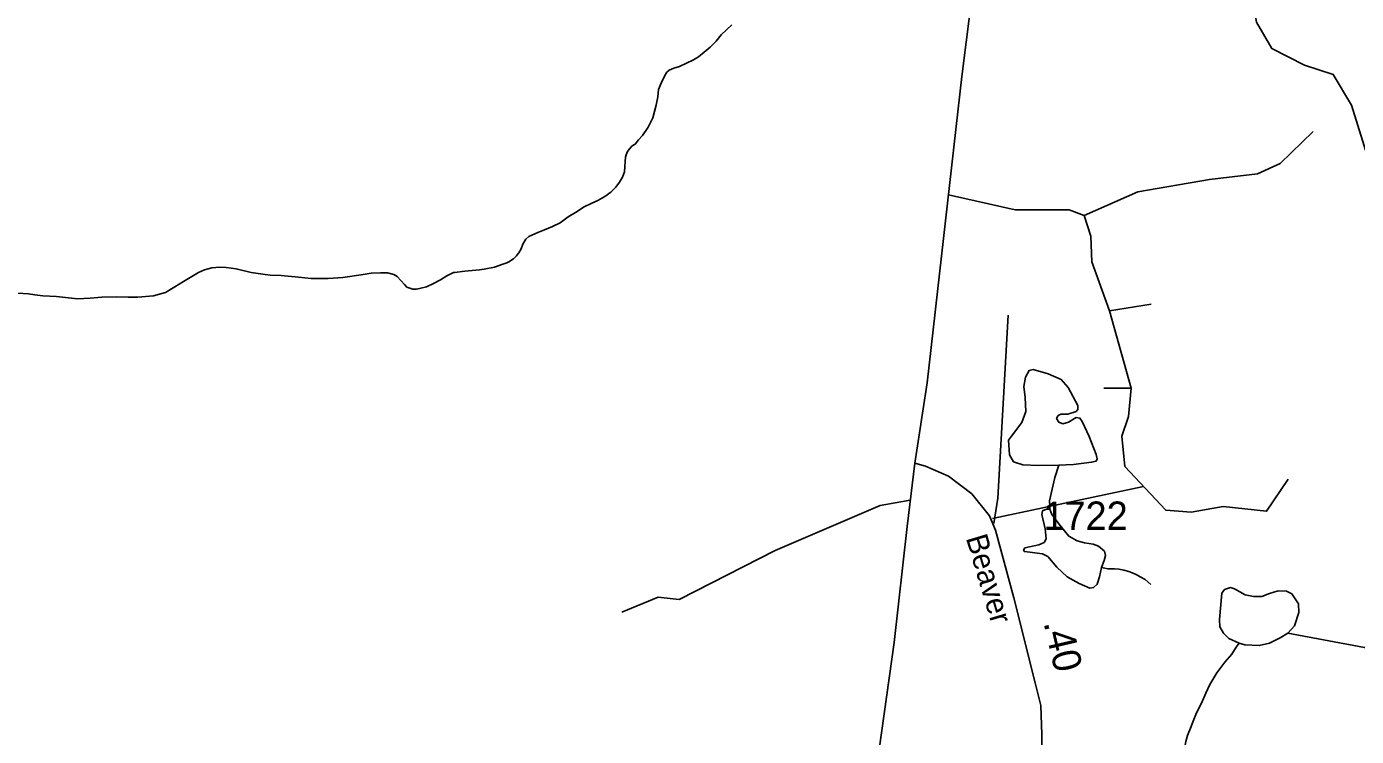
# Model space of a CAD drawing. Extents: x 2056842 to 2160602, y 826753 to 1016856.
# Drawn here: x 2087342 to 2093202, y 850532 to 853660 of the extents above; entities that cross this region are included whole.
import ezdxf

# ---------------------------------------------------------------- set-up
doc = ezdxf.new("R2010")
doc.units = 0
for name, color, linetype in [('Exist Hydrographic Creek Single Shore', 7, 'Continuous'), ('Exist Hydrographic Misc Water Feature', 7, 'Continuous'), ('Exist Road Non-System Type 51', 7, 'Continuous'), ('Exist Road Primary NC Attributed', 7, 'Continuous'), ('Exist Road Secondary Mileage Hundredths English Label', 7, 'Continuous'), ('Exist Road Secondary Type 51 Attributed', 7, 'Continuous'), ('Exist Road Secondary Type 51 Label', 7, 'Continuous'), ('Exist Road Secondary Type 51 Number Label', 7, 'Continuous')]:
    doc.layers.add(name, color=color, linetype=linetype)

msp = doc.modelspace()

# ---------------------------------------------------------------- linework, layer by layer
at = {"layer": 'Exist Hydrographic Creek Single Shore'}
for points in [[(2094262.8, 851850.9), (2094137.2, 852037.8), (2094000.5, 852284.8), (2093797.5, 852514.6), (2093629.1, 852735.1), (2093557.8, 852881.1), (2093520.2, 852910.4), (2093445.5, 852933.2), (2093359.2, 852968.7), (2093264.2, 853045.4), (2093180.1, 853313), (2093099.6, 853448.9), (2092973, 853489.4), (2092829.3, 853562.9), (2092762.2, 853679.2), (2092728.2, 853870.2), (2092751.4, 854356.6), (2092797, 854536.5)], [(2090449.8, 853667.4), (2090402, 853623.1), (2090380.1, 853595.2), (2090354.5, 853569), (2090328.2, 853547), (2090302.4, 853527), (2090280.4, 853512.9), (2090250.5, 853498.8), (2090218.3, 853484.5), (2090194.5, 853476.4), (2090172.8, 853468.3), (2090162.5, 853458.6), (2090152.9, 853440.6), (2090138.9, 853410.2), (2090127.1, 853382.4), (2090123, 853350.1), (2090116.8, 853314.1), (2090101.2, 853258.1), (2090081.5, 853216.4), (2090055.5, 853180.2), (2090037.7, 853160.2), (2090023.7, 853142), (2090010, 853134), (2089999.9, 853122.1), (2089989.9, 853109.8), (2089983.7, 853094.1), (2089981.7, 853083.9), (2089980, 853065.9), (2089978, 853041.8), (2089976.1, 853019.8), (2089968.3, 852995.8), (2089954, 852974), (2089938.4, 852951.7), (2089916.5, 852929.8), (2089890, 852911.5), (2089858.6, 852893.5), (2089830.3, 852879.6), (2089798.6, 852865.3), (2089760.6, 852841), (2089728.8, 852821.1), (2089692.5, 852795), (2089658.9, 852779), (2089624.7, 852764.7), (2089595.1, 852752.9), (2089555.2, 852734.7), (2089541.2, 852722.6), (2089528.9, 852700.5), (2089520.9, 852680.6), (2089511.3, 852662.6), (2089503.5, 852654.4), (2089501, 852650.3), (2089487.3, 852636.6), (2089467.6, 852622.6), (2089457.6, 852618.4), (2089441.2, 852612.4), (2089403.4, 852600.2), (2089357.7, 852590.1), (2089337.2, 852587.9), (2089273.4, 852581.8), (2089227.3, 852575.8), (2089223.4, 852575.5), (2089193.5, 852561.4), (2089165.4, 852543.4), (2089135.4, 852527.2)], [(2089135.4, 852527.2), (2089103.4, 852513.4), (2089079.4, 852507.3), (2089059.8, 852503), (2089044, 852503), (2089017.7, 852511), (2089007.7, 852523.1), (2088991.7, 852540.9), (2088975.5, 852558.8), (2088959.5, 852566.9), (2088931.8, 852574.7), (2088901.7, 852574.8), (2088859.6, 852572.7), (2088815.7, 852566.4), (2088735.8, 852554.1), (2088671.4, 852550.1), (2088595.7, 852549.8), (2088539.7, 852555.4), (2088463.7, 852563.3), (2088415.5, 852564.9), (2088383.5, 852569), (2088331.6, 852576.8), (2088265.4, 852592.5), (2088221.3, 852598.4), (2088193.6, 852600.2), (2088157.7, 852596.3), (2088125.3, 852588.2), (2088099.5, 852576.3), (2088033.9, 852536), (2087995.7, 852513.7), (2087953.9, 852487.6), (2087901.8, 852473.6), (2087831.9, 852467.1), (2087789.9, 852467), (2087736.1, 852469.1), (2087673.8, 852466.8), (2087622.1, 852462.4), (2087566.2, 852460.4), (2087513.9, 852466.3), (2087474.3, 852470.3), (2087414, 852474), (2087378.1, 852477.9), (2087350, 852481.8), (2087302.3, 852485.8)], [(2092899.2, 850987.5), (2093237.1, 850923.1), (2093362.2, 850963.2), (2093719.2, 851313.5), (2093899.2, 851549.4), (2094034.7, 851679.9), (2094262.8, 851850.9)]]:
    msp.add_lwpolyline(points, dxfattribs=at)
at = {"layer": 'Exist Hydrographic Misc Water Feature'}
for points in [[(2091890.5, 851727.5), (2091801.2, 851725), (2091731.5, 851728.7), (2091691.2, 851742.1), (2091672.8, 851772.7), (2091669.1, 851837.6), (2091681.4, 851854.7), (2091727.9, 851914.7), (2091745, 851963.7), (2091742.5, 852024.9), (2091736.4, 852073.8), (2091743.8, 852115.4), (2091759.7, 852143.6), (2091778, 852148.5), (2091842.8, 852130.1), (2091901.5, 852104.4), (2091932.1, 852070.1), (2091973.7, 851989.4), (2091974.9, 851972.2), (2091966.4, 851963.7), (2091930.9, 851952.6), (2091899.1, 851952.6), (2091886.9, 851945.3), (2091880.7, 851933.1), (2091890.5, 851917.2), (2091907.6, 851909.8), (2091933.3, 851917.2), (2091966.4, 851936.7), (2091983.5, 851934.3), (2091993.3, 851919.6), (2092023.8, 851853.5), (2092054.4, 851774), (2092059.3, 851754.4), (2092054.4, 851744.6), (2092034.9, 851739.7), (2091955.4, 851729.9), (2091890.5, 851727.5)], [(2091850.3, 851533.9), (2091850.3, 851546), (2091850.1, 851570), (2091873.4, 851672.9), (2091890.5, 851727.5)], [(2091850.3, 851533.9), (2091835.5, 851533.7), (2091818.4, 851525.2), (2091815.9, 851509.2), (2091830.6, 851446.8), (2091834.3, 851402.8), (2091825.7, 851386.9), (2091802.5, 851375.8), (2091741.3, 851362.4), (2091735.2, 851352.6), (2091738.9, 851346.5), (2091762.1, 851344), (2091818.4, 851336.7), (2091841.6, 851324.4), (2091882, 851277.9), (2091927.2, 851235.1), (2091979.8, 851205.7), (2092027.5, 851184.9), (2092043.4, 851187.4), (2092059.3, 851203.3), (2092069.1, 851235.1), (2092079.1, 851276.9)], [(2092079.1, 851276.9), (2092089.9, 851307.3), (2092096, 851329.3), (2092091.1, 851347.7), (2092065.4, 851369.7), (2092042.2, 851379.5), (2092004.3, 851385.6), (2091971.3, 851394.2), (2091934.6, 851415), (2091896.6, 851461.5), (2091859.9, 851509.2), (2091850.3, 851533.9)], [(2092295.3, 851201.5), (2092271.3, 851223.4), (2092248.9, 851235.3), (2092231.1, 851245.3), (2092213.3, 851253.3), (2092198.9, 851259.1), (2092177, 851264.9), (2092155.2, 851269), (2092135.1, 851270.8), (2092115, 851271), (2092107, 851271), (2092093.3, 851272.6), (2092079.1, 851276.9)], [(2092685, 850943), (2092639.6, 850963.4), (2092615.6, 850987.5), (2092600.4, 851015.4), (2092599.1, 851047), (2092609.2, 851163.6), (2092620.6, 851178.8), (2092647.2, 851187.7), (2092665, 851182.6), (2092711.8, 851156), (2092748.5, 851148.4), (2092785.2, 851148.4), (2092818.2, 851161.1), (2092857.4, 851173.7), (2092894.1, 851172.5), (2092916.9, 851159.8), (2092946, 851116.7), (2092948.6, 851077.5), (2092929.6, 851019.2), (2092899.2, 850987.5)], [(2092899.2, 850987.5), (2092866.3, 850966), (2092819.4, 850943.2), (2092773.8, 850931.8), (2092710.5, 850935.6), (2092685, 850943)], [(2092685, 850943), (2092672, 850924.5), (2092652.5, 850894.6), (2092622.1, 850858.6), (2092586.4, 850812.5), (2092556.5, 850760.2), (2092538.7, 850722.3), (2092519.2, 850678.3), (2092497.3, 850636.1), (2092479.2, 850592.2), (2092473.3, 850576), (2092457.1, 850535.8), (2092449.5, 850509.9), (2092443.5, 850469.8), (2092439.8, 850424.1), (2092435.9, 850387.7), (2092438, 850370), (2092442.1, 850345.8), (2092440, 850323.8)]]:
    msp.add_lwpolyline(points, dxfattribs=at)
at = {"layer": 'Exist Road Non-System Type 51'}
for p, q in [((2092114.2, 852407.5), (2092297, 852436.6)), ((2092114.2, 852407.5), (2092209.8, 852066.6)), ((2092209.8, 852066.6), (2092089.3, 852066.6)), ((2091597.8, 851492), (2092263.8, 851632.6))]:
    msp.add_line(p, q, dxfattribs=at)
for points in [[(2092002.1, 852827.3), (2092238.8, 852931.3), (2092554.5, 852985.3), (2092766.4, 853010.2), (2092866.1, 853056), (2093011.5, 853197.3)], [(2091404.4, 852918.1), (2091698.8, 852852.3), (2091935.6, 852852.3), (2092002.1, 852827.3)], [(2092002.1, 852827.3), (2092031.1, 852735.9), (2092035.3, 852623.6), (2092114.2, 852407.5)], [(2091603.8, 851469.8), (2091622, 851582.3), (2091667.7, 852388.8)], [(2092209.8, 852066.6), (2092197.3, 851941.9), (2092168.2, 851854.6), (2092180.7, 851721.6), (2092361.4, 851528.3), (2092473.5, 851520), (2092614.8, 851544.9), (2092805.9, 851524.2), (2092901.4, 851665.5)], [(2091236.1, 851572.5), (2091103.8, 851550.1), (2090640.6, 851350.6), (2090217.9, 851135.5), (2090124.4, 851145.9), (2089964.5, 851079.4)]]:
    msp.add_lwpolyline(points, dxfattribs=at)
at = {"layer": 'Exist Road Primary NC Attributed'}
for points in [[(2091255.4, 851735.3), (2091310.7, 852089.3), (2091463.3, 853439.2), (2091613.9, 854639.5), (2091758.2, 855835.6), (2091801.9, 856136.9), (2091910.9, 857004.6), (2091950.4, 857347.6), (2092044.9, 858101), (2092082.2, 858431.4), (2092170.5, 859143.2), (2092214.1, 859513.2), (2092249.2, 859809.6)], [(2090793.8, 848076.9), (2090829.9, 848397.1), (2090890.1, 848806.6), (2090995, 849693), (2091022, 849929.9), (2091164.2, 850945.2), (2091222.4, 851456.5), (2091255.4, 851735.3)]]:
    msp.add_lwpolyline(points, dxfattribs=at)
at = {"layer": 'Exist Road Secondary Type 51 Attributed'}
msp.add_lwpolyline([(2091255.4, 851735.3), (2091303.1, 851722.8), (2091404.9, 851679.2), (2091506.7, 851600.2), (2091585.6, 851504.6), (2091611.6, 851441.2), (2091692.6, 851141.9), (2091786, 850767.8), (2091810.9, 850668.1), (2091816.1, 850540.2), (2091814.6, 850368.3), (2091822.9, 850187.4), (2091830.2, 850007.7)], dxfattribs=at)

# ---------------------------------------------------------------- texts
at = {"layer": 'Exist Road Secondary Mileage Hundredths English Label'}
msp.add_text('.40', height=125, rotation=283.11089, dxfattribs=at).set_placement((2091822.5, 851033.3))
at = {"layer": 'Exist Road Secondary Type 51 Label'}
msp.add_text('Beaver', height=95, rotation=286.57785, dxfattribs=at).set_placement((2091480.4, 851406.6))
at = {"layer": 'Exist Road Secondary Type 51 Number Label'}
msp.add_text('1722', height=125, dxfattribs=at).set_placement((2091822.3, 851442))

doc.saveas('drawing.dxf')
